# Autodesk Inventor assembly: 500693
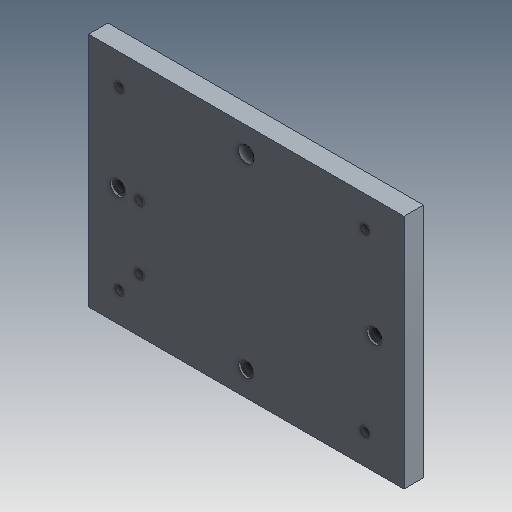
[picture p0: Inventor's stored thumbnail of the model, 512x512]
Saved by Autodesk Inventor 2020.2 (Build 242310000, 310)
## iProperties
Created: 2000-02
Part Number: 500693
Document SubType Name: Assembly
Description: PLT-XX,FA,XX,05,080,060,BUCKET_MOUNT
Designer: glanglot
Mass: 1046.86 g
Surface Area: 774.463 cm^2
Volume: 381.564 cm^3
Density: 2.74361 g/cm^3
Control State: 0
Checked Out: False
Master: False
Shininess: 0.0
Length Units: 11272
Angle Units: 11279
Time Units: 11290
Mass Units: 11286
Length Display Precision: 3
Angle Display Precision: 2
Compacted: True
Dimensions: 6x0,5x8 in
Mass: 2,308 lb
Density: 0.0
Volumn: 0.0
Area: 0.0
PropertySet Name: Model Information
Author: glanglot
Revision Number: -
Title: PLT-XX,FA,XX,05,080,060,BUCKET_MOUNT
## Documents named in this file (4)
- D:\07 - DEMODATEN\OTX 2019 - Dataset - UPDATE - Dez2019\Designs\07-Packing machine\500693.iam
- D:\07 - DEMODATEN\OTX 2019 - Dataset - UPDATE - Dez2019\Designs\07-Packing machine\Parts\ADSK-011677.ipt
- D:\07 - DEMODATEN\OTX 2019 - Dataset - UPDATE - Dez2019\Designs\07-Packing machine\Parts\ADSK-011736.ipt
- D:\07 - DEMODATEN\OTX 2019 - Dataset - UPDATE - Dez2019\Designs\07-Packing machine\Parts\ADSK-011737.ipt
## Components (10 placed, 3 different names)
1. ADSK-011677:1 — Insert:1, Insert:2, Insert:3, Insert:4, Insert:5, Insert:6, Insert:7, Insert:8, Insert:9
2. ADSK-011736:1 — Insert:8
3. ADSK-011736:2 — Insert:9
4. ADSK-011736:3 — Insert:1
5. ADSK-011737:1 — Insert:2
6. ADSK-011737:2 — Insert:4
7. ADSK-011737:3 — Insert:5
8. ADSK-011737:4 — Insert:3
9. ADSK-011737:5 — Insert:6
10. ADSK-011737:6 — Insert:7
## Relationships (9: Insert 9)
- Insert:1: ADSK-011677:1 ↔ ADSK-011736:3
- Insert:2: ADSK-011677:1 ↔ ADSK-011737:1
- Insert:3: ADSK-011677:1 ↔ ADSK-011737:4
- Insert:4: ADSK-011677:1 ↔ ADSK-011737:2
- Insert:5: ADSK-011677:1 ↔ ADSK-011737:3
- Insert:6: ADSK-011677:1 ↔ ADSK-011737:5
- Insert:7: ADSK-011677:1 ↔ ADSK-011737:6
- Insert:8: ADSK-011677:1 ↔ ADSK-011736:1
- Insert:9: ADSK-011677:1 ↔ ADSK-011736:2
